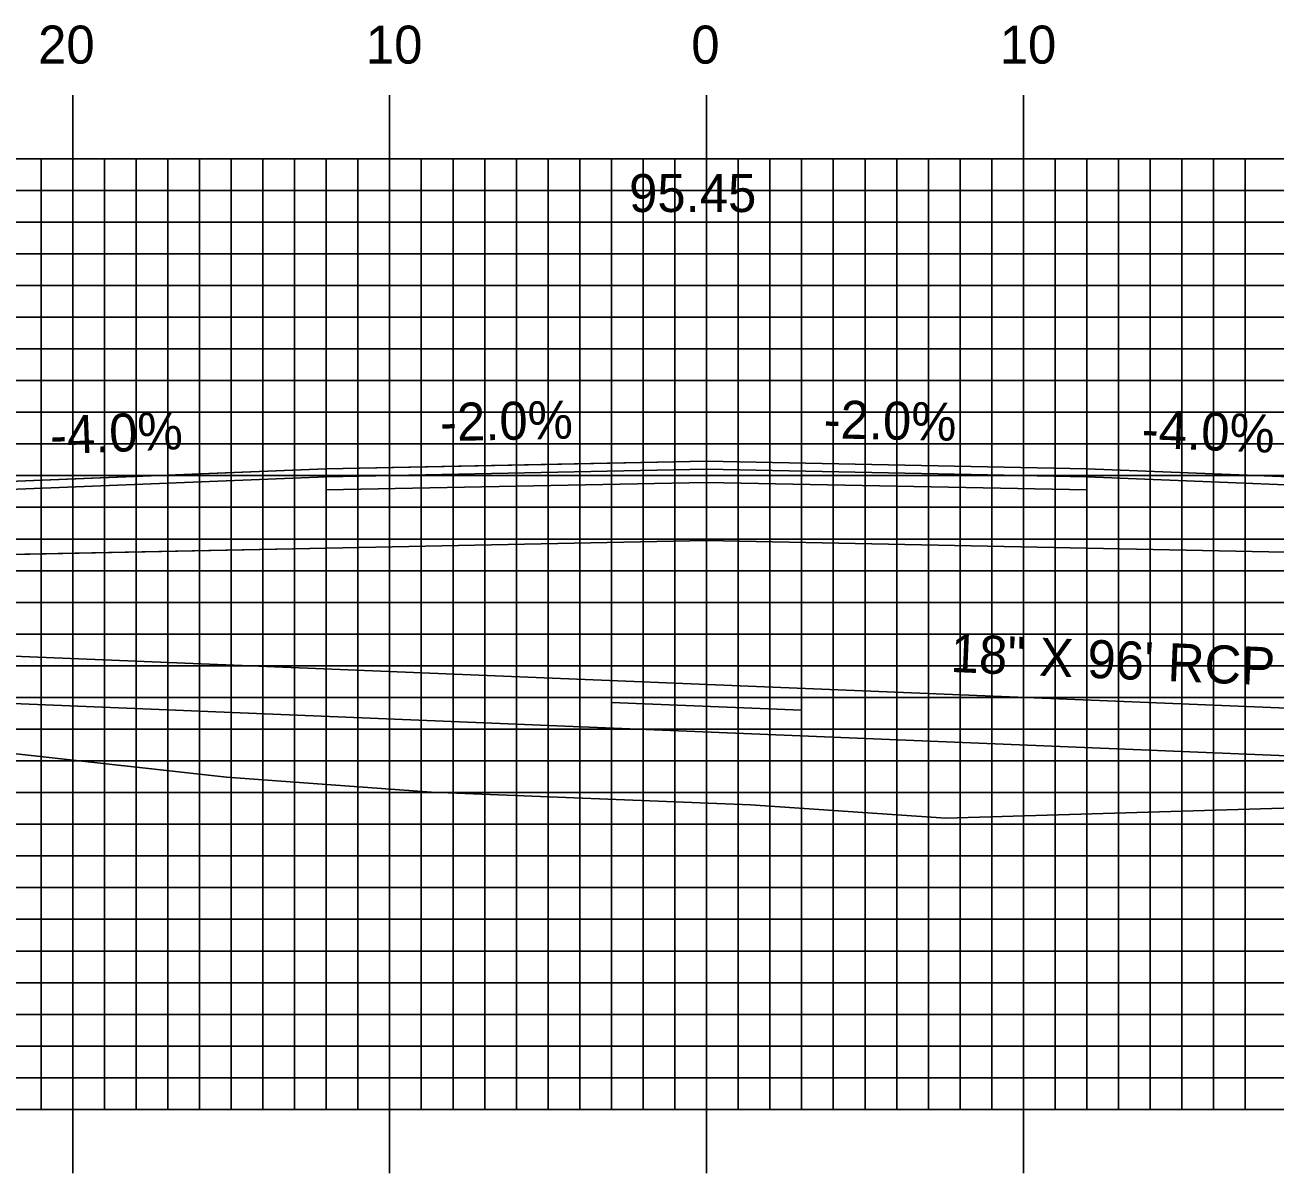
# Model space of a CAD drawing. Extents: x 1775564 to 1775907, y 442591 to 442811.
# Drawn here: x 1775708.21 to 1775747.65, y 442731.66 to 442767.88 of the extents above; entities that cross this region are included whole.
import ezdxf

# ---------------------------------------------------------------- set-up
doc = ezdxf.new("R2010")
doc.units = 0
for name, color, linetype in [('ANNOTATION', 7, 'Continuous'), ('D_Drainage_Culvert', 7, 'Continuous'), ('D_Drainage_Text', 7, 'Continuous'), ('D_Roadway_Centerline', 7, 'Continuous'), ('D_Roadway_Centerline_Text', 7, 'Continuous'), ('D_Roadway_Edge_Shoulder', 7, 'Continuous'), ('D_Roadway_Edge_TW', 7, 'Continuous'), ('D_Roadway_Pavement', 7, 'Continuous'), ('D_Roadway_SubGrade', 7, 'Continuous'), ('H_V ANNOTATION', 7, 'Continuous'), ('MAJOR', 7, 'Continuous'), ('MINOR', 7, 'Continuous'), ('S_Roadway_Centerline', 7, 'Continuous')]:
    doc.layers.add(name, color=color, linetype=linetype)

msp = doc.modelspace()

# ---------------------------------------------------------------- linework, layer by layer
at = {"layer": 'ANNOTATION'}
for p, q in [((1775717.706, 442753.212), (1775717.706, 442751.378)), ((1775741.706, 442753.212), (1775741.706, 442751.378)), ((1775717.706, 442751.378), (1775693.913, 442750.903)), ((1775729.706, 442751.618), (1775717.706, 442751.378)), ((1775741.706, 442751.378), (1775729.706, 442751.618))]:
    msp.add_line(p, q, dxfattribs=at)
at = {"layer": 'D_Drainage_Culvert'}
for p, q in [((1775780.029, 442745.014), (1775684.11, 442748.945)), ((1775684.048, 442747.446), (1775779.968, 442743.515)), ((1775726.711, 442746.507), (1775732.711, 442746.261))]:
    msp.add_line(p, q, dxfattribs=at)
at = {"layer": 'D_Roadway_Centerline'}
msp.add_lwpolyline([(1775688.612, 442749.728), (1775693.913, 442750.903), (1775705.062, 442753.373), (1775705.062, 442753.373), (1775705.066, 442753.373), (1775709.262, 442753.541), (1775717.699, 442753.879), (1775717.706, 442753.879), (1775717.713, 442753.879), (1775724.629, 442754.017), (1775729.701, 442754.119), (1775729.706, 442754.119), (1775729.711, 442754.119), (1775741.706, 442753.879), (1775749.707, 442753.559), (1775752.706, 442753.439), (1775758.651, 442751.456), (1775758.652, 442751.456), (1775774.914, 442746.036)], dxfattribs=at)
at = {"layer": 'D_Roadway_Edge_Shoulder'}
for points in [[(1775717.706, 442753.879), (1775705.062, 442753.373), (1775705.062, 442753.123), (1775717.706, 442753.629)], [(1775741.706, 442753.879), (1775749.706, 442753.559), (1775749.706, 442753.559), (1775752.706, 442753.439), (1775752.706, 442753.189), (1775741.706, 442753.629)]]:
    msp.add_lwpolyline(points, close=True, dxfattribs=at)
at = {"layer": 'D_Roadway_Edge_TW'}
msp.add_lwpolyline([(1775717.706, 442753.629), (1775717.706, 442753.879), (1775729.706, 442754.119), (1775741.706, 442753.879), (1775741.706, 442753.629), (1775729.706, 442753.869)], close=True, dxfattribs=at)
at = {"layer": 'D_Roadway_Pavement'}
msp.add_lwpolyline([(1775717.706, 442753.212), (1775717.706, 442753.629), (1775729.706, 442753.869), (1775741.706, 442753.629), (1775741.706, 442753.212), (1775729.706, 442753.452)], close=True, dxfattribs=at)
at = {"layer": 'D_Roadway_SubGrade'}
for points in [[(1775717.706, 442751.378), (1775717.706, 442753.629), (1775729.706, 442753.869), (1775741.706, 442753.629), (1775741.706, 442751.378), (1775729.706, 442751.618)], [(1775717.706, 442751.378), (1775693.914, 442750.903), (1775705.062, 442753.373), (1775705.062, 442753.123), (1775717.706, 442753.629)], [(1775741.706, 442753.629), (1775752.706, 442753.189), (1775752.706, 442753.439), (1775759.981, 442751.013), (1775741.706, 442751.378)]]:
    msp.add_lwpolyline(points, close=True, dxfattribs=at)
at = {"layer": 'MAJOR'}
for p, q in [((1775709.711, 442765.669), (1775709.711, 442763.665)), ((1775719.711, 442765.669), (1775719.711, 442763.665)), ((1775729.711, 442765.669), (1775729.711, 442763.665)), ((1775739.711, 442765.669), (1775739.711, 442763.665)), ((1775589.711, 442763.665), (1775869.711, 442763.665)), ((1775589.711, 442763.665), (1775869.711, 442763.665)), ((1775709.711, 442733.665), (1775709.711, 442763.665)), ((1775719.711, 442733.665), (1775719.711, 442763.665)), ((1775729.711, 442733.665), (1775729.711, 442763.665)), ((1775739.711, 442733.665), (1775739.711, 442763.665)), ((1775589.711, 442758.665), (1775869.711, 442758.665)), ((1775589.711, 442753.665), (1775869.711, 442753.665)), ((1775589.711, 442748.665), (1775869.711, 442748.665)), ((1775589.711, 442743.665), (1775869.711, 442743.665)), ((1775589.711, 442738.665), (1775869.711, 442738.665)), ((1775589.711, 442733.665), (1775869.711, 442733.665)), ((1775589.711, 442733.665), (1775869.711, 442733.665)), ((1775709.711, 442731.661), (1775709.711, 442733.665)), ((1775719.711, 442731.661), (1775719.711, 442733.665)), ((1775729.711, 442731.661), (1775729.711, 442733.665)), ((1775739.711, 442731.661), (1775739.711, 442733.665))]:
    msp.add_line(p, q, dxfattribs=at)
at = {"layer": 'MINOR'}
for p, q in [((1775708.711, 442733.665), (1775708.711, 442763.665)), ((1775710.711, 442733.665), (1775710.711, 442763.665)), ((1775711.711, 442733.665), (1775711.711, 442763.665)), ((1775712.711, 442733.665), (1775712.711, 442763.665)), ((1775713.711, 442733.665), (1775713.711, 442763.665)), ((1775714.711, 442733.665), (1775714.711, 442763.665)), ((1775715.711, 442733.665), (1775715.711, 442763.665)), ((1775716.711, 442733.665), (1775716.711, 442763.665)), ((1775717.711, 442733.665), (1775717.711, 442763.665)), ((1775718.711, 442733.665), (1775718.711, 442763.665)), ((1775720.711, 442733.665), (1775720.711, 442763.665)), ((1775721.711, 442733.665), (1775721.711, 442763.665)), ((1775722.711, 442733.665), (1775722.711, 442763.665)), ((1775723.711, 442733.665), (1775723.711, 442763.665)), ((1775724.711, 442733.665), (1775724.711, 442763.665)), ((1775725.711, 442733.665), (1775725.711, 442763.665)), ((1775726.711, 442733.665), (1775726.711, 442763.665)), ((1775727.711, 442733.665), (1775727.711, 442763.665)), ((1775728.711, 442733.665), (1775728.711, 442763.665)), ((1775730.711, 442733.665), (1775730.711, 442763.665)), ((1775731.711, 442733.665), (1775731.711, 442763.665)), ((1775732.711, 442733.665), (1775732.711, 442763.665)), ((1775733.711, 442733.665), (1775733.711, 442763.665)), ((1775734.711, 442733.665), (1775734.711, 442763.665)), ((1775735.711, 442733.665), (1775735.711, 442763.665)), ((1775736.711, 442733.665), (1775736.711, 442763.665)), ((1775737.711, 442733.665), (1775737.711, 442763.665)), ((1775738.711, 442733.665), (1775738.711, 442763.665)), ((1775740.711, 442733.665), (1775740.711, 442763.665)), ((1775741.711, 442733.665), (1775741.711, 442763.665)), ((1775742.711, 442733.665), (1775742.711, 442763.665)), ((1775743.711, 442733.665), (1775743.711, 442763.665)), ((1775744.711, 442733.665), (1775744.711, 442763.665)), ((1775745.711, 442733.665), (1775745.711, 442763.665)), ((1775746.711, 442733.665), (1775746.711, 442763.665)), ((1775589.711, 442762.665), (1775869.711, 442762.665)), ((1775589.711, 442761.665), (1775869.711, 442761.665)), ((1775589.711, 442760.665), (1775869.711, 442760.665)), ((1775589.711, 442759.665), (1775869.711, 442759.665)), ((1775589.711, 442757.665), (1775869.711, 442757.665)), ((1775589.711, 442756.665), (1775869.711, 442756.665)), ((1775589.711, 442755.665), (1775869.711, 442755.665)), ((1775589.711, 442754.665), (1775869.711, 442754.665)), ((1775589.711, 442752.665), (1775869.711, 442752.665)), ((1775589.711, 442751.665), (1775869.711, 442751.665)), ((1775589.711, 442750.665), (1775869.711, 442750.665)), ((1775589.711, 442749.665), (1775869.711, 442749.665)), ((1775589.711, 442747.665), (1775869.711, 442747.665)), ((1775589.711, 442746.665), (1775869.711, 442746.665)), ((1775589.711, 442745.665), (1775869.711, 442745.665)), ((1775589.711, 442744.665), (1775869.711, 442744.665)), ((1775589.711, 442742.665), (1775869.711, 442742.665)), ((1775589.711, 442741.665), (1775869.711, 442741.665)), ((1775589.711, 442740.665), (1775869.711, 442740.665)), ((1775589.711, 442739.665), (1775869.711, 442739.665)), ((1775589.711, 442737.665), (1775869.711, 442737.665)), ((1775589.711, 442736.665), (1775869.711, 442736.665)), ((1775589.711, 442735.665), (1775869.711, 442735.665)), ((1775589.711, 442734.665), (1775869.711, 442734.665))]:
    msp.add_line(p, q, dxfattribs=at)
at = {"layer": 'S_Roadway_Centerline'}
msp.add_lwpolyline([(1775672.883, 442748.755), (1775679.808, 442747.944), (1775686.03, 442747.238), (1775692.236, 442746.554), (1775708.023, 442744.873), (1775714.564, 442744.146), (1775721.037, 442743.68), (1775731.103, 442743.28), (1775737.266, 442742.856), (1775752.875, 442743.315), (1775759.742, 442742.762), (1775767.868, 442743.076), (1775772.092, 442743.041), (1775776.145, 442743.138), (1775784.349, 442743.456), (1775792.415, 442743.856)], dxfattribs=at)

# ---------------------------------------------------------------- texts
at = {"layer": 'ANNOTATION'}
for s, rotation, p in [('-2.0%', 1.1457, (1775721.313, 442754.751)), ('-2.0%', 358.8543, (1775733.395, 442754.845)), ('-4.0%', 2.2918, (1775709.014, 442754.333)), ('-4.0%', 357.7094, (1775743.427, 442754.549))]:
    msp.add_text(s, height=1.2, rotation=rotation, dxfattribs=at).set_placement(p)
at = {"layer": 'D_Drainage_Text'}
msp.add_text('18" X 96\' RCP', height=1.2, rotation=357.5812, dxfattribs=at).set_placement((1775737.394, 442747.472))
at = {"layer": 'D_Roadway_Centerline_Text'}
msp.add_text('95.45', height=1.2, dxfattribs=at).set_placement((1775727.266, 442761.982))
at = {"layer": 'H_V ANNOTATION'}
for s, p in [('20', (1775708.619, 442766.665)), ('10', (1775718.962, 442766.665)), ('0', (1775729.23, 442766.665)), ('10', (1775738.962, 442766.665))]:
    msp.add_text(s, height=1.2, dxfattribs=at).set_placement(p)

doc.saveas('drawing.dxf')
